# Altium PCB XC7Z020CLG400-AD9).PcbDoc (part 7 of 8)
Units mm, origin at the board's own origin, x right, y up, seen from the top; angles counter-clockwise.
Board outline 38 x 38 mm, 14 copper layers (Top Layer, GND02, ART03, PWR04, ART05, GND06, ART07, ART08, PWR09, ART10, GND11, ART12, PWR13, Bottom Layer); 276 components, 302 nets, 1684 pads, 1576 vias.
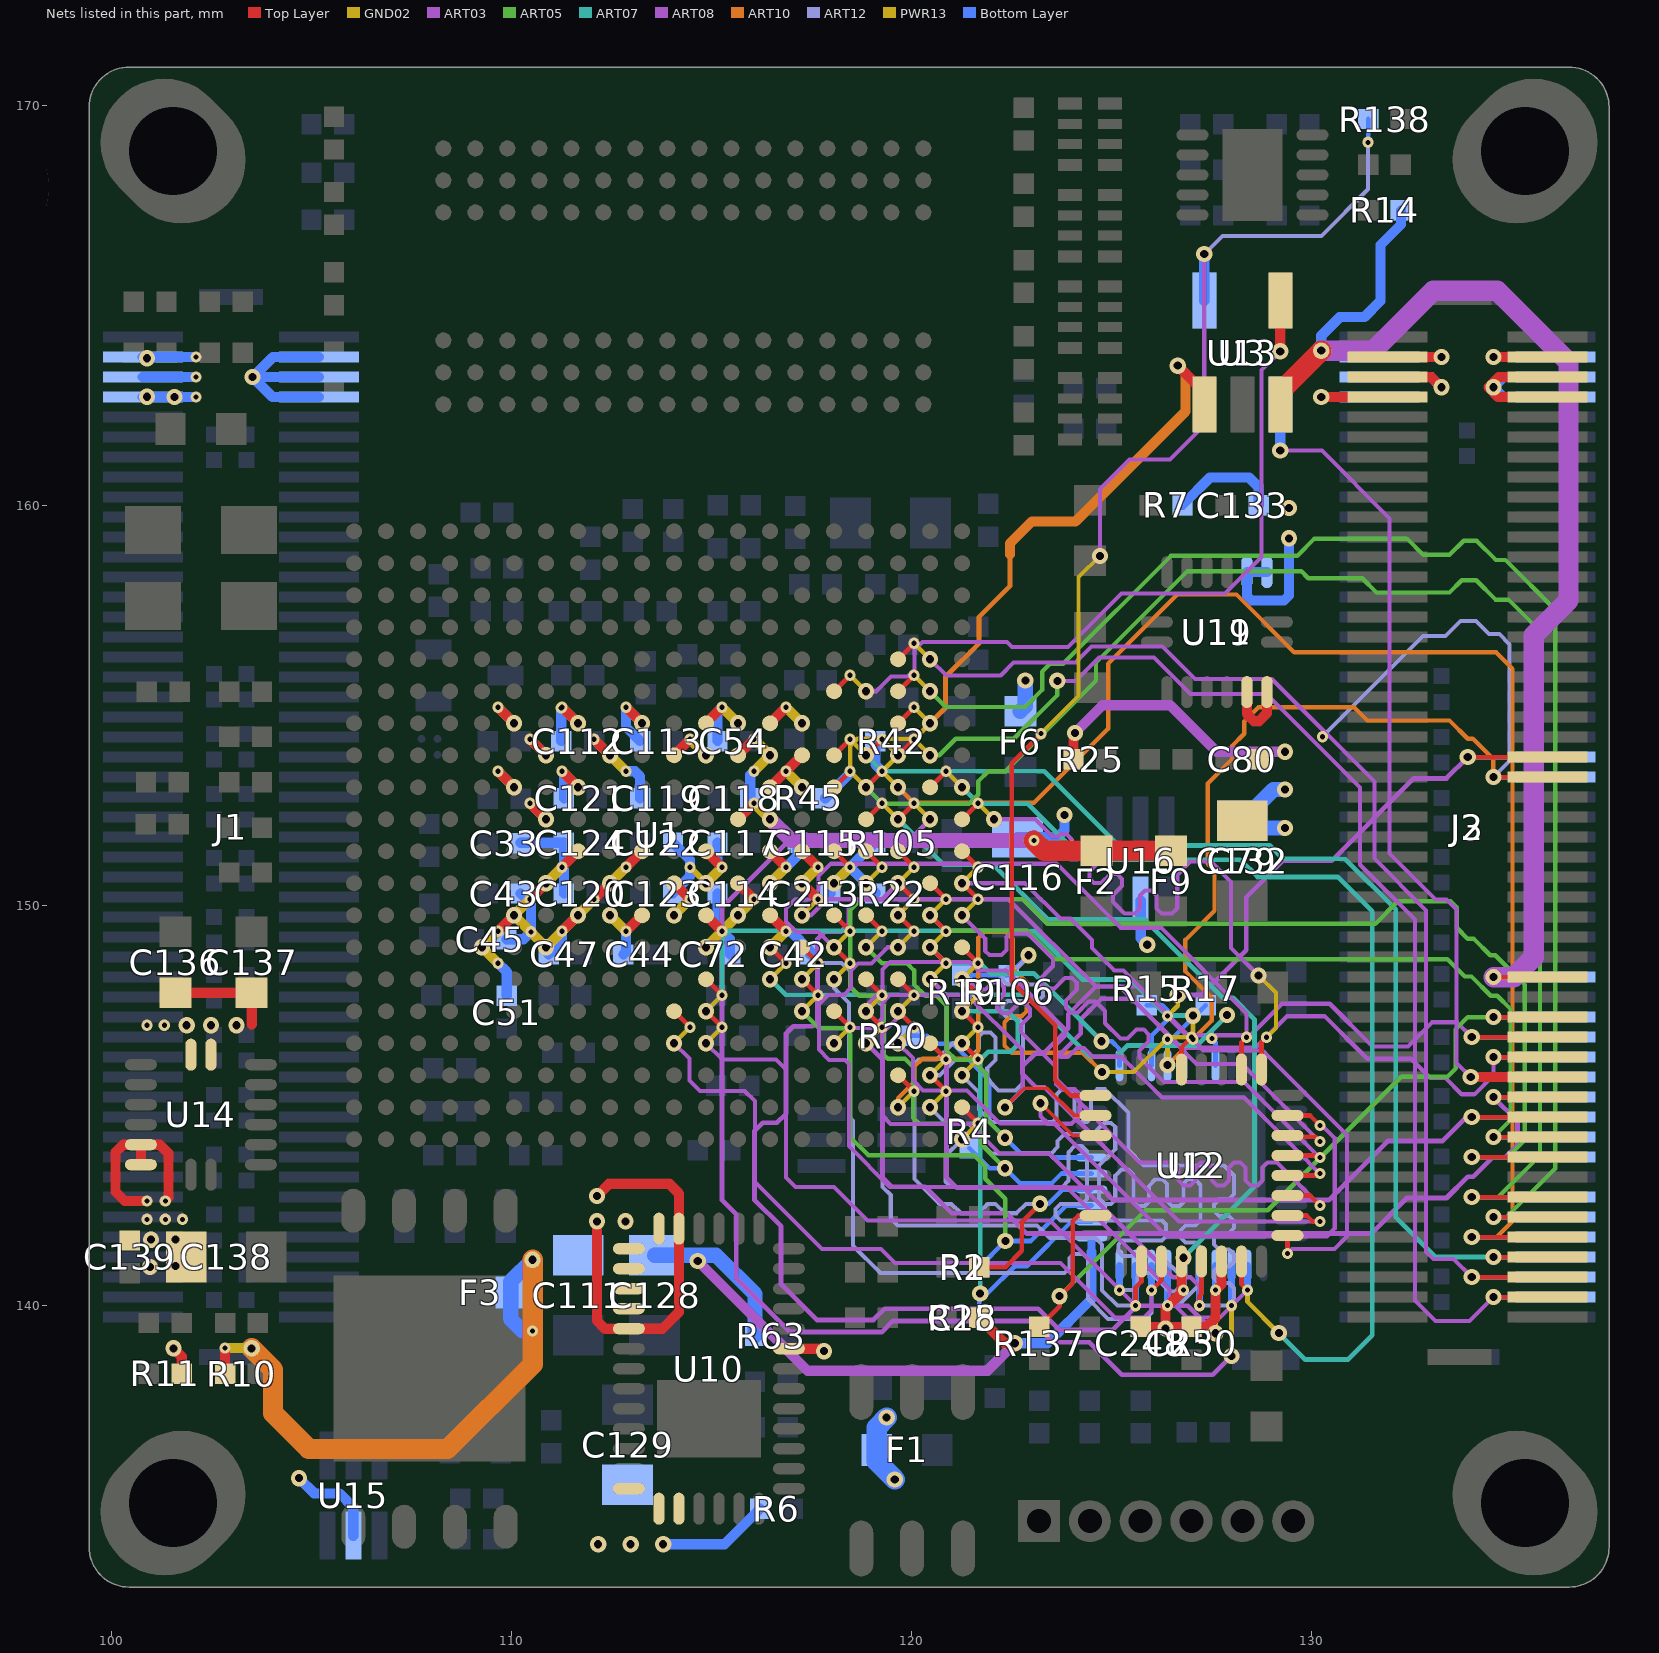
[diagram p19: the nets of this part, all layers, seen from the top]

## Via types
v1: diameter 0.406, hole 0.203, GND02 to PWR13, 466 vias
v2: diameter 0.279, hole 0.127, Top Layer to GND02, tented top, 373 vias
v3: diameter 0.406, hole 0.203, Top Layer to Bottom Layer, 324 vias
v4: diameter 0.279, hole 0.127, PWR13 to Bottom Layer, 207 vias
v5: diameter 0.279, hole 0.127, Top Layer to ART03, tented top, 41 vias
v6: diameter 0.279, hole 0.127, Top Layer to ART03, 40 vias
v7: diameter 0.279, hole 0.127, PWR13 to Bottom Layer, tented bottom, 39 vias
v8: diameter 0.279, hole 0.127, ART12 to Bottom Layer, 30 vias
v9: diameter 0.279, hole 0.127, Top Layer to GND02, 20 vias
v10: diameter 0.406, hole 0.203, Top Layer to Bottom Layer, tented both sides, 16 vias
v11: diameter 0.406, hole 0.203, ART03 to ART12, 11 vias
v12: diameter 0.406, hole 0.203, Top Layer to Bottom Layer, tented top, 9 vias

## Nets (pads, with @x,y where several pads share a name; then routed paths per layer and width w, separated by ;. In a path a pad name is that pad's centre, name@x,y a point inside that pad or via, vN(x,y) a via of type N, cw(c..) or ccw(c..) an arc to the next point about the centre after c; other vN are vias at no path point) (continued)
PHY_LED1: J2.29 J3.29 R15.1 U2.33 | length 17.4
  Top Layer w0.114: v3(133.905,153.719) J3.29@135.9,153.719
  ART08 w0.119: v1(126.657,147.772) 127.248,147.772 128.372,148.895 128.372,150.216 129.286,151.13 130.505,151.13 132.563,153.187 133.374,153.187 v3(133.905,153.719)
  PWR13 w0.114: v4(126.4,147.246) 126.657,147.503 v1(126.657,147.772)
  Bottom Layer w0.114: R15.1@125.882,147.52 126.267,147.52 126.4,147.387 v4(126.4,147.246) 126.4,147.152 126,146.752 U2.33@126,146.01 ; v3(133.905,153.719) J2.29@136.1,153.719
PHY_LED2: J2.28 J3.28 R17.1 U2.34 | length 32.5
  Top Layer w0.114: v3(134.548,153.219) J3.28@135.9,153.219
  ART10 w0.109: v1(126.4,146.025) 127.508,147.133 127.508,147.701 126.848,148.361 126.848,149.149 127.575,149.876 127.575,150.885 127.406,151.054 127.406,153.06 128.016,153.67 128.016,154 128.321,154.305 128.321,154.61 128.676,154.965 131.064,154.965 131.394,154.635 133.452,154.635 133.909,154.178 134.036,154.178 134.548,153.665 v3(134.548,153.219)
  ART12 w0.102: v8(130.277,154.229) 132.791,156.743 133.35,156.743 133.731,157.124 134.112,157.124 134.442,156.794 134.696,156.794 134.95,156.54 134.95,153.621 v3(134.548,153.219)
  PWR13 w0.114: v1(126.4,146.025) v4(126.4,146.666)
  Bottom Layer w0.114: U2.34@126.4,146.01 v4(126.4,146.666) 126.502,146.666 R17.1@127.356,147.52 ; v3(134.548,153.219) J2.28@136.1,153.219
PS-MIO-VREF: C213.1 R22.1 R105.2 U1.E11 | length 4.4
  Top Layer w0.114: U1.E11@118.065,151.365 v2(118.465,150.965)
  GND02 w0.109: v1(118.065,150.565) v2(118.465,150.965)
  PWR13 w0.254: v1(118.065,150.565) v2(118.465,150.965)
  Bottom Layer w0.254: C213.1@117.971,150.309 117.971,150.471 v2(118.465,150.965) ; R22.1@119.097,150.309 119.097,150.333 v2(118.465,150.965) ; R105.2@119.097,151.579 119.079,151.579 v2(118.465,150.965)
  other v4: 118.465,150.965
RGMII-CLK25M: U1.G14 U2.37 | length 15.2
  Top Layer w0.114: U1.G14@116.465,148.965 v2(116.865,148.565)
  ART12 w0.102: v8(127.508,146.685) 127.508,146.888 v1(127.889,147.269)
  GND02 w0.109: v1(116.465,148.165) v2(116.865,148.565)
  ART07 w0.119: v1(116.465,148.165) 116.853,147.777 122.911,147.777 124.46,146.228 125.12,146.228 125.4,146.507 127.127,146.507 v1(127.889,147.269)
  Bottom Layer w0.114: v8(127.508,146.685) 127.6,146.593 U2.37@127.6,146.01
RGMII-CLK125M: U1.J15 U2.35 | length 17.2
  Top Layer w0.114: U1.J15@114.865,148.165 v2(115.265,147.765)
  GND02 w0.109: v1(114.865,147.365) v2(115.265,147.765)
  ART07 w0.119: v1(114.865,147.365) v2(115.265,147.765) 115.265,149.2 115.443,149.377 123.063,149.377 124.282,148.158 125.476,148.158 126.378,147.256 v1(127.038,147.256)
  PWR13 w0.114: v4(127.038,146.666) v1(127.038,147.256)
  Bottom Layer w0.114: U2.35@126.8,146.01 126.8,146.428 v4(127.038,146.666)
RGMII-MDC: U1.C10 U2.13 | length 32.7
  Top Layer w0.114: U1.C10@119.665,152.165 v2(120.065,152.565)
  GND02 w0.109: v2(120.065,152.565) v1(120.465,152.165)
  ART08 w0.119: v1(120.465,152.165) 120.015,151.715 117.018,151.715 115.265,149.962 115.265,142.646 115.621,142.291 115.621,140.691 116.967,139.344 119.253,139.344 119.532,139.624 122.994,139.624 123.527,139.09 124.448,139.09 125.261,138.278 127.533,138.278 v1(128,138.744)
  PWR13 w0.114: v1(128,138.744) v4(128,140.005)
  Bottom Layer w0.178: v4(128,140.005) U2.13@128,141.01
RGMII-MDIO: R3.2 U1.C11 U2.14 | length 29.2
  Top Layer w0.114: U1.C11@119.665,151.365 v2(120.065,150.965)
  GND02 w0.109: v1(119.665,150.565) v2(120.065,150.965)
  ART08 w0.119: v1(119.665,150.565) 119.265,150.165 118.618,150.165 118.44,149.987 118.44,149.555 118.237,149.352 117.831,149.352 117.653,149.174 117.653,147.117 117.526,146.99 117.043,146.99 116.865,146.812 116.865,144.805 116.637,144.577 116.281,144.577 116.078,144.374 116.078,142.646 116.738,141.986 116.738,140.545 117.634,139.649 119.05,139.649 119.329,139.929 123.172,139.929 123.705,139.395 125.019,139.395 125.628,140.005 126.912,140.005 v1(127.6,139.317)
  PWR13 w0.114: v1(127.6,139.317) v4(127.6,140.392)
  Bottom Layer w0.114: R3.2@127,139.475 127.391,139.475 127.6,139.684 v4(127.6,140.392)
  Bottom Layer w0.178: v4(127.6,140.392) U2.14@127.6,141.01
RGMII-NINT: U1.B13 U2.31 | length 7.3
  Top Layer w0.114: U1.B13@120.465,149.765 v2(120.865,149.365)
  GND02 w0.109: v1(120.465,148.965) v2(120.865,149.365)
  ART07 w0.119: v1(120.465,148.965) 120.865,148.565 121.717,148.565 121.971,148.311 123.056,148.311 v3(124.752,146.615)
  Bottom Layer w0.114: v3(124.752,146.615) 125.006,146.615 125.2,146.421 U2.31@125.2,146.01
RGMII-NRST: U1.B9 U2.12 | length 28.1
  Top Layer w0.114: U1.B9@120.465,152.965 v2(120.865,153.365)
  GND02 w0.109: v2(120.865,153.365) v1(121.265,152.965)
  ART07 w0.119: v1(121.265,152.965) 121.678,152.552 122.911,152.552 124.308,151.155 128.219,151.155 128.651,150.724 130.658,150.724 131.521,149.86 131.521,139.268 130.912,138.659 129.845,138.659 v1(129.184,139.319)
  PWR13 w0.114: v4(128.4,140.392) 128.4,140.103 v1(129.184,139.319)
  Bottom Layer w0.178: v4(128.4,140.392) U2.12@128.4,141.01
RGMII-RXCLK: R19.1 R106.1 U1.B17 | length 13.2
  Top Layer w0.114: U1.B17@120.465,146.565 v2(120.865,146.165)
  ART12 w0.102: v1(120.465,145.765) 120.695,145.765 121.082,146.152 121.412,146.152 121.691,146.431 121.691,146.736 121.793,146.837 121.971,146.837 122.098,146.71 122.098,146.152 121.895,145.948 121.895,145.669 122.174,145.39 122.606,145.39 122.784,145.567 122.784,147.074 122.658,147.199 122.401,147.199 122.276,147.325 122.276,147.493 122.401,147.618 123.166,147.618 123.292,147.744 123.292,147.912 123.166,148.038 122.401,148.038 122.276,148.163 122.276,148.331 122.401,148.457 122.658,148.457 122.784,148.582 122.784,148.62 v3(122.928,148.764)
  GND02 w0.109: v1(120.465,145.765) v2(120.865,146.165)
  Bottom Layer w0.114: R19.1@121.265,148.264 R106.1@122.428,148.264 v3(122.928,148.764)
RGMII-RXCTL: R20.1 U1.D13 U2.26 | length 14.5
  Top Layer w0.114: U1.D13@118.865,149.765 v2(119.265,149.365)
  ART05 w0.109: v1(118.865,148.965) 119.265,148.565 119.888,148.565 120.066,148.387 120.066,148.031 120.345,147.752 120.625,147.752 120.879,147.498 120.879,146.38 121.107,146.152 121.514,146.152 121.869,145.796 121.869,144.672 v3(122.339,144.202)
  GND02 w0.109: v1(118.865,148.965) v2(119.265,149.365)
  Bottom Layer w0.114: R20.1@119.956,146.753 120.379,146.753 120.574,146.558 121.031,146.558 121.945,145.644 121.945,144.596 v3(122.339,144.202) 122.72,143.821 123.438,143.821 123.549,143.71 U2.26@124.5,143.71
RGMII-RXD0: R4.1 U1.D11 U2.25 | length 14.8
  Top Layer w0.114: U1.D11@118.865,151.365 v2(119.265,150.965)
  ART05 w0.109: v1(118.865,150.565) 118.865,150.285 118.466,149.885 118.466,147.98 118.694,147.752 119.075,147.752 119.304,147.523 119.304,146.279 119.405,146.177 119.837,146.177 120.04,145.974 120.04,144.704 120.193,144.551 121.514,144.551 121.742,144.323 121.742,144.037 v3(122.339,143.44)
  GND02 w0.109: v1(118.865,150.565) v2(119.265,150.965)
  Bottom Layer w0.114: R4.1@121.451,143.941 121.951,143.44 v3(122.339,143.44) 122.72,143.059 123.501,143.059 123.752,143.31 U2.25@124.5,143.31
RGMII-RXD1: R1.1 U1.A16 U2.24 | length 13.2
  Top Layer w0.114: U1.A16@121.265,147.365 v2(121.665,146.965) ; R1.1@121.695,140.97 122.352,140.97 122.758,141.376 122.758,142.094 v3(123.215,142.551)
  ART12 w0.102: v1(121.265,146.565) 121.038,146.565 120.632,146.159 120.174,146.159 120.073,146.057 120.073,143.173 120.695,142.551 121.006,142.551 121.24,142.316 121.66,142.316 121.895,142.551 122.098,142.551 122.333,142.316 122.625,142.316 122.86,142.551 v3(123.215,142.551)
  GND02 w0.109: v1(121.265,146.565) v2(121.665,146.965)
  Bottom Layer w0.114: v3(123.215,142.551) 123.425,142.551 123.784,142.91 U2.24@124.5,142.91
RGMII-RXD2: R2.1 U1.F15 U2.23 | length 14.4
  Top Layer w0.114: U1.F15@117.265,148.165 v2(117.665,147.765)
  ART05 w0.109: v1(117.265,147.365) 117.691,146.939 118.313,146.939 118.466,146.787 118.466,144.221 118.923,143.764 121.564,143.764 121.844,143.485 121.844,143.18 122.347,142.677 v3(122.347,141.622)
  GND02 w0.109: v1(117.265,147.365) v2(117.665,147.765)
  Bottom Layer w0.114: R2.1@121.695,140.97 v3(122.347,141.622) 122.978,141.622 123.866,142.51 U2.23@124.5,142.51
  Bottom Layer w0.381: R2.1@121.695,140.97 R2.1@121.695,141.018
RGMII-RXD3: R18.2 U1.A15 U2.22 | length 14.3
  Top Layer w0.114: U1.A15@121.265,148.165 v2(121.665,147.765)
  GND02 w0.109: v1(121.265,147.365) v2(121.665,147.765)
  ART07 w0.119: v1(121.265,147.365) 122.408,147.365 122.657,147.117 122.657,146.533 122.479,146.355 121.92,146.355 121.717,146.152 v3(121.717,140.31)
  Bottom Layer w0.114: R18.2@121.695,139.7 v3@121.695,140.288 ; v3@121.717,140.288 v3@121.695,140.288 ; U2.22@124.5,142.11 124,142.11 122.885,140.995 122.58,140.995 121.895,140.31 v3(121.717,140.31) v3@121.695,140.288
RGMII-TXCLK: U1.A19 U2.20 | length 18.5
  Top Layer w0.114: U1.A19@121.265,144.965 v2(121.665,144.565)
  ART12 w0.102: v1(121.265,144.165) 120.853,143.753 120.853,143.104 120.98,142.977 123.774,142.977 123.927,143.129 123.927,143.84 124.079,143.993 124.257,143.993 124.384,143.866 124.384,142.672 124.257,142.545 123.723,142.545 123.596,142.418 123.596,142.265 123.723,142.138 126.263,142.138 126.365,142.037 126.365,141.732 126.263,141.63 125.273,141.63 125.171,141.529 125.171,141.351 125.273,141.249 126.238,141.249 126.771,140.716 126.771,140.538 126.594,140.36 126.445,140.36 125.987,140.818 125.755,140.818 125.654,140.716 125.654,140.487 125.558,140.392 v8(125.2,140.392)
  GND02 w0.109: v1(121.265,144.165) v2(121.665,144.565)
  Bottom Layer w0.178: v8(125.2,140.392) U2.20@125.2,141.01
RGMII-TXCTL: U1.F14 U2.19 | length 18.1
  Top Layer w0.114: U1.F14@117.265,148.965 v2(117.665,148.565)
  ART12 w0.102: v1(117.265,148.165) 117.672,148.572 118.255,148.572 118.472,148.355 118.472,147.98 118.676,147.777 118.999,147.777 119.278,147.498 119.278,142.977 119.482,142.773 119.482,142.189 119.659,142.011 123.139,142.011 123.457,141.694 124.6,141.694 124.765,141.529 124.765,140.386 125.146,140.005 v8(125.6,140.005)
  GND02 w0.109: v1(117.265,148.165) v2(117.665,148.565)
  Bottom Layer w0.178: v8(125.6,140.005) U2.19@125.6,141.01
RGMII-TXD0: U1.E14 U2.18 | length 18.6
  Top Layer w0.114: U1.E14@118.065,148.965 v2(118.465,148.565)
  ART12 w0.102: v1(118.065,148.165) 118.065,147.949 118.44,147.574 118.44,144.729 118.542,144.628 118.542,141.503 119.228,140.818 123.825,140.818 123.952,140.945 123.952,141.199 124.054,141.3 124.282,141.3 124.409,141.173 124.409,140.183 124.917,139.675 125.857,139.675 126,139.818 v8(126,140.392)
  GND02 w0.109: v1(118.065,148.165) v2(118.465,148.565)
  Bottom Layer w0.178: v8(126,140.392) U2.18@126,141.01
RGMII-TXD1: U1.B18 U2.17 | length 19.7
  Top Layer w0.114: U1.B18@120.465,145.765 v2(120.865,145.365)
  ART12 w0.102: v1(120.465,144.965) 120.879,144.551 121.437,144.551 121.717,144.272 121.717,144.094 121.996,143.815 123.495,143.815 123.647,143.967 123.647,144.12 123.825,144.297 124.536,144.297 124.816,144.577 124.993,144.577 125.095,144.475 125.095,143.916 124.689,143.51 124.689,142.697 124.841,142.545 124.993,142.545 125.095,142.646 125.095,143.256 125.247,143.408 125.425,143.408 125.552,143.281 125.552,142.596 125.654,142.494 125.832,142.494 125.933,142.596 125.933,143.002 126.086,143.154 126.289,143.154 126.39,143.053 126.39,142.621 126.517,142.494 126.695,142.494 126.797,142.596 126.797,143.053 126.898,143.154 127.102,143.154 127.229,143.027 127.229,142.131 127.103,142.005 126.846,142.005 126.721,141.879 126.721,141.712 126.846,141.586 127.103,141.586 127.229,141.46 127.229,140.564 126.67,140.005 v8(126.4,140.005)
  GND02 w0.109: v1(120.465,144.965) v2(120.865,145.365)
  Bottom Layer w0.178: v8(126.4,140.005) U2.17@126.4,141.01
RGMII-TXD2: U1.D10 U2.16 | length 20.2
  Top Layer w0.114: U1.D10@118.865,152.165 v2(119.265,152.565)
  GND02 w0.109: v2(119.265,152.565) v1(119.665,152.165)
  ART07 w0.119: v1(119.665,152.165) 120.802,151.028 122.047,151.028 123.419,149.657 125.832,149.657 127.787,147.701 128.041,147.701 128.575,147.168 128.575,142.977 v1(126.8,141.202)
  PWR13 w0.109: v4(126.8,140.392) v1(126.8,141.202)
  Bottom Layer w0.178: v4(126.8,140.392) U2.16@126.8,141.01
RGMII-TXD3: U1.A17 U2.15 | length 19.3
  Top Layer w0.114: U1.A17@121.265,146.565 v2(121.665,146.165)
  ART12 w0.102: v1(121.265,145.765) 121.691,145.339 121.691,144.907 121.996,144.602 123.52,144.602 123.622,144.704 123.622,145.288 123.749,145.415 123.927,145.415 124.079,145.263 124.079,144.704 124.181,144.602 124.384,144.602 124.485,144.704 124.485,145.263 124.638,145.415 124.841,145.415 125.425,144.831 125.425,143.891 125.806,143.51 127.813,143.51 128.067,143.256 128.067,142.791 127.941,142.665 127.685,142.665 127.559,142.54 127.559,142.372 127.685,142.246 127.941,142.246 128.067,142.121 128.067,141.953 127.941,141.827 127.685,141.827 127.559,141.702 127.559,141.534 127.685,141.408 127.941,141.408 128.067,141.282 128.067,141.115 127.941,140.989 127.685,140.989 127.559,140.863 127.559,140.696 127.685,140.57 127.941,140.57 128.067,140.444 128.067,140.157 127.915,140.005 v8(127.2,140.005)
  GND02 w0.109: v1(121.265,145.765) v2(121.665,146.165)
  Bottom Layer w0.178: v8(127.2,140.005) U2.15@127.2,141.01
SPI1_CLK_CAN1_RX: J2.10 J3.10 U1.B12 | length 22.9
  Top Layer w0.114: U1.B12@120.465,150.565 v2(120.865,150.165) ; v3(134.548,144.219) J3.10@135.9,144.219
  ART05 w0.109: v1(120.465,149.765) 120.853,149.377 122.885,149.377 123.594,148.669 133.398,148.669 133.833,148.234 134,148.234 134.483,147.752 134.645,147.752 134.976,147.422 134.976,144.646 v3(134.548,144.219)
  GND02 w0.109: v1(120.465,149.765) v2(120.865,150.165)
  Bottom Layer w0.114: v3(134.548,144.219) J2.10@136.1,144.219
SPI1_CS0_CAN1_TX: J2.9 J3.9 U1.C12 | length 28
  Top Layer w0.114: U1.C12@119.665,150.565 v2(120.065,150.165) ; v3(134.007,143.719) J3.9@135.9,143.719
  ART05 w0.109: v1(119.665,149.765) 120.04,150.14 120.04,150.165 ; v2(120.065,150.165) 122.784,150.165 123.393,149.555 131.597,149.555 132.156,150.114 133.477,150.114 133.629,149.962 133.629,149.454 133.909,149.174 134.061,149.174 134.468,148.768 134.595,148.768 135.331,148.031 135.331,144.145 134.905,143.719 v3(134.007,143.719)
  GND02 w0.109: v1(119.665,149.765) v2(120.065,150.165)
  Bottom Layer w0.114: v3(134.007,143.719) J2.9@136.1,143.719
SPI1_MISO_CAN0_TX: J2.11 J3.11 U1.B14 | length 24.5
  Top Layer w0.114: U1.B14@120.465,148.965 v2(120.865,148.565) ; v3(134.007,144.719) J3.11@135.9,144.719
  GND02 w0.109: v1(120.465,148.165) v2(120.865,148.565)
  ART08 w0.119: v1(120.465,148.165) 120.879,147.751 120.879,143.205 121.133,142.951 124.739,142.951 125.044,142.646 130.429,142.646 131.902,144.12 133.274,144.12 133.873,144.719 v3(134.007,144.719)
  Bottom Layer w0.114: v3(134.007,144.719) J2.11@136.1,144.719
SPI1_MOSI_CAN0_RX: J2.12 J3.12 U1.D16 | length 26.4
  Top Layer w0.114: U1.D16@118.865,147.365 v2(119.265,146.965) ; v3(134.548,145.219) J3.12@135.9,145.219
  GND02 w0.109: v1(118.865,146.565) v2(119.265,146.965)
  ART08 w0.119: v1(118.865,146.565) 119.278,146.152 119.278,143.205 119.507,142.977 120.345,142.977 121.006,142.316 122.377,142.316 122.885,141.808 131.496,141.808 132.385,142.697 133.375,142.697 133.909,143.231 134.044,143.231 134.527,143.713 134.849,143.713 135.153,144.018 135.153,144.614 v3(134.548,145.219)
  Bottom Layer w0.114: v3(134.548,145.219) J2.12@136.1,145.219
UART-RXA: J2.7 J3.7 U1.E9 | length 41.1
  Top Layer w0.114: U1.E9@118.065,152.965 v2(118.465,153.365) ; v3(134.007,142.719) J3.7@135.9,142.719
  ART05 w0.109: v1(118.865,152.965) 119.278,152.552 121.437,152.552 121.666,152.781 121.666,153.111 121.92,153.365 122.352,153.365 124.612,155.626 124.612,156.083 126.898,158.369 129.743,158.369 129.921,158.191 131.267,158.191 131.623,157.836 133.452,157.836 133.756,158.14 134.119,158.14 134.601,157.658 134.925,157.658 135.712,156.87 135.712,143.761 134.671,142.719 v3(134.007,142.719)
  GND02 w0.109: v2(118.465,153.365) v1(118.865,152.965)
  Bottom Layer w0.114: v3(134.007,142.719) J2.7@136.1,142.719
UART-RXB: J2.4 J3.4 U1.E8 | length 29.4
  Top Layer w0.114: U1.E8@118.065,153.765 v2(118.465,154.165) ; v3(134.548,141.219) J3.4@135.9,141.219
  GND02 w0.109: v2(118.465,154.165) v1(118.865,153.765)
  ART07 w0.119: v1(118.865,153.765) 119.265,153.365 123.317,153.365 125.171,151.511 128.956,151.511 129.286,151.181 130.835,151.181 132.105,149.911 132.105,142.215 133.101,141.219 v3(134.548,141.219)
  Bottom Layer w0.114: v3(134.548,141.219) J2.4@136.1,141.219
UART-TXA: J2.6 J3.6 U1.C6 | length 38.9
  Top Layer w0.114: U1.C6@119.665,155.365 v2(120.065,155.765) ; v3(134.548,142.219) J3.6@135.9,142.219
  ART05 w0.109: v1(120.465,155.365) 120.858,154.972 122.841,154.972 123.266,155.397 123.266,155.854 123.469,156.058 123.793,156.058 126.485,158.75 129.642,158.75 130.073,159.182 132.385,159.182 132.791,158.775 133.452,158.775 133.807,159.131 134.128,159.131 134.611,158.648 134.849,158.648 136.093,157.404 136.093,143.434 134.879,142.219 v3(134.548,142.219)
  GND02 w0.109: v2(120.065,155.765) v1(120.465,155.365)
  Bottom Layer w0.114: v3(134.548,142.219) J2.6@136.1,142.219
UART-TXB: J2.5 J3.5 U1.D9 | length 39.5
  Top Layer w0.114: U1.D9@118.865,152.965 v2(119.265,153.365) ; v3(134.007,141.719) J3.5@135.9,141.719
  ART10 w0.109: v1(119.665,152.965) 120.052,152.578 123.063,152.578 124.917,154.432 124.917,156.058 126.644,157.785 128.124,157.785 129.572,156.337 134.62,156.337 135.026,155.931 135.026,142.113 134.633,141.719 v3(134.007,141.719)
  GND02 w0.109: v2(119.265,153.365) v1(119.665,152.965)
  Bottom Layer w0.114: v3(134.007,141.719) J2.5@136.1,141.719
USB0-CLK: U1.J16 U12.26 | length 17.3
  Top Layer w0.114: U1.J16@114.865,147.365 v2(115.265,146.965) ; v6(125.6,140.005) 125.6,140.459 125.75,140.609 U12.26@125.75,141.11
  ART03 w0.102: v1(114.865,146.565) 115.271,146.159 116.618,146.159 116.865,145.911 116.865,143.212 117.101,142.977 118.059,142.977 118.897,142.138 123.467,142.138 v6(125.6,140.005)
  GND02 w0.109: v1(114.865,146.565) v2(115.265,146.965)
USB0-CLKO: U1.A11 U12.1 | length 18.1
  Top Layer w0.114: U1.A11@121.265,151.365 v2(121.665,150.965) ; v6(129.4,141.313) U12.1@129.4,141.76
  ART03 w0.102: v1(121.265,150.565) 122.841,150.565 123.723,149.682 123.977,149.682 124.511,149.149 124.511,148.946 125.07,148.387 125.298,148.387 127.305,146.38 128.778,146.38 130.886,144.272 130.886,141.732 130.576,141.422 129.508,141.422 v6(129.4,141.313)
  GND02 w0.109: v1(121.265,150.565) v2(121.665,150.965)
USB0-CPEN: R138.1 U12.17 U13.4 | length 32.5
  Top Layer w0.114: v9(123.241,154.305) 122.504,153.568 122.504,148.107 123.596,147.015 123.596,145.644 123.98,145.26 U12.17@124.6,145.26
  ART03 w0.102: v1(124.714,158.75) 124.714,160.426 125.451,161.163 126.467,161.163 127.32,162.016 v3(127.32,166.295)
  ART12 w0.102: v3(127.32,166.295) 127.776,166.751 130.251,166.751 131.416,167.916 v8(131.416,169.089)
  GND02 w0.102: v9(123.241,154.305) 124.181,155.245 124.181,158.217 v1(124.714,158.75)
  Bottom Layer w0.114: v8@131.416,169.084 v8(131.416,169.089) R138.1@131.416,169.672
  Bottom Layer w0.254: U13.4@127.32,165.13 v3(127.32,166.295)
USB0-D0: U1.A14 U12.3 | length 17.6
  Top Layer w0.114: U1.A14@121.265,148.965 v2(121.665,148.565) ; U12.3@129.4,142.76 129.963,142.76 v6(130.213,142.51)
  ART03 w0.102: v1(121.265,148.165) 121.419,148.165 121.67,147.914 121.848,147.914 122.018,148.083 122.195,148.083 122.314,147.965 122.314,147.787 122.144,147.617 122.144,147.439 122.263,147.321 122.441,147.321 122.667,147.547 122.845,147.547 122.963,147.429 122.963,147.251 122.737,147.025 122.737,146.847 123.596,145.987 123.596,145.694 125.705,143.586 126.55,143.586 126.676,143.46 126.676,143.14 126.802,143.015 126.97,143.015 127.095,143.14 127.095,143.46 127.221,143.586 127.389,143.586 127.514,143.46 127.514,143.14 127.64,143.015 127.808,143.015 127.933,143.14 127.933,143.46 128.059,143.586 128.227,143.586 128.353,143.46 128.353,143.14 128.478,143.015 128.646,143.015 128.772,143.14 128.772,143.46 128.897,143.586 129.137,143.586 v6(130.213,142.51)
  GND02 w0.109: v1(121.265,148.165) v2(121.665,148.565)
USB0-D1: U1.D15 U12.4 | length 17.1
  Top Layer w0.114: U1.D15@118.865,148.165 v2(119.265,147.765) ; U12.4@129.4,143.26 130.163,143.26 v6(130.213,143.31)
  ART03 w0.102: v1@118.865,147.491 119.273,147.899 119.273,148.407 119.463,148.597 121.456,148.597 121.666,148.387 122.377,148.387 123.837,146.927 123.837,146.749 123.611,146.522 123.611,146.345 123.73,146.226 123.908,146.226 124.134,146.452 124.312,146.452 124.536,146.228 125.247,146.228 126.263,145.212 128.311,145.212 129.921,143.602 ; 129.921,143.589 v6@130.2,143.31
  GND02 w0.109: v1(118.865,147.365) v2(119.265,147.765)
USB0-D2: U1.A12 U12.5 | length 17.2
  Top Layer w0.114: U1.A12@121.265,150.565 v2(121.665,150.165) ; U12.5@129.4,143.76 130.163,143.76 v6(130.213,143.71)
  ART03 w0.102: v1(121.265,149.765) 121.844,149.186 121.844,148.869 121.945,148.768 122.25,148.768 122.377,148.895 122.377,149.206 122.479,149.307 122.905,149.307 123.539,148.673 123.539,148.495 123.268,148.224 123.268,148.046 123.386,147.928 123.564,147.928 123.835,148.199 124.013,148.199 124.131,148.08 124.131,147.902 123.86,147.631 123.86,147.453 123.979,147.335 124.157,147.335 124.428,147.606 124.606,147.606 124.841,147.371 124.841,147.066 125.225,146.682 125.403,146.682 125.63,146.908 125.807,146.908 125.926,146.789 125.926,146.611 125.7,146.385 125.7,146.207 126.314,145.593 128.317,145.593 v6@130.2,143.71
  GND02 w0.109: v1(121.265,149.765) v2(121.665,150.165)
USB0-D3: U1.F12 U12.6 | length 17.6
  Top Layer w0.114: U12.6@129.4,144.26 129.436,144.224 130.099,144.224 v6(130.213,144.11)
  Top Layer w0.254: U1.F12@117.265,150.565 v2(117.665,150.165)
  ART03 w0.102: v1(117.265,149.765) 117.482,149.765 117.882,150.165 122.428,150.165 124.612,147.98 125.197,147.98 127.127,146.05 128.26,146.05 130.2,144.11 v6(130.213,144.11)
  GND02 w0.109: v1(117.265,149.765) v2(117.665,150.165)
USB0-D4: U1.C16 U12.7 | length 18.1
  Top Layer w0.114: U1.C16@119.665,147.365 v2(120.065,146.965) ; U12.7@129.4,144.76 129.963,144.76 v6(130.213,144.51)
  ART03 w0.102: v1(119.665,146.565) 120.035,146.196 120.035,145.644 120.289,145.39 121.387,145.39 122.219,144.558 123.565,144.558 126.383,141.739 130.385,141.739 130.581,141.935 130.581,144.196 130.267,144.51 v6(130.213,144.51)
  GND02 w0.109: v1(119.665,146.565) v2(120.065,146.965)
USB0-D5: U1.A10 U12.9 | length 17.6
  Top Layer w0.114: U1.A10@121.265,152.165 v2(121.665,152.565) ; U12.9@128.75,145.91 128.75,146.589 v9(128.877,146.716)
  ART03 w0.102: v1(122.065,152.165) 123.095,152.165 123.52,151.74 123.673,151.74 123.731,151.797 123.875,151.797 124.018,151.653 124.018,151.51 123.876,151.367 123.876,151.257 123.973,151.16 124.151,151.16 124.377,151.386 124.555,151.386 124.674,151.267 124.674,151.09 124.447,150.863 124.447,150.685 124.566,150.567 124.744,150.567 124.97,150.793 125.148,150.793 125.266,150.675 125.266,150.497 125.04,150.271 125.04,150.093 125.324,149.809 125.585,149.809 125.711,149.935 125.711,150.255 125.837,150.381 126.004,150.381 126.13,150.255 126.13,149.935 126.256,149.809 126.517,149.809 126.644,149.936 126.644,150.774 126.975,151.105 127.483,151.105 127.991,150.597 127.991,148.946 v1(128.676,148.26)
  GND02 w0.102: v1(128.676,148.26) 129.108,147.828 129.108,146.947 v9(128.877,146.716)
  GND02 w0.109: v2(121.665,152.565) v1(122.065,152.165)
USB0-D6: U1.E13 U12.10 | length 18.1
  Top Layer w0.114: U1.E13@118.065,149.765 v2(118.465,149.365) ; U12.10@128.25,145.91 128.25,146.589 v6(128.377,146.716)
  ART03 w0.102: v1(118.065,148.965) 117.678,149.352 117.119,149.352 116.865,149.606 116.865,149.936 117.094,150.165 117.45,150.165 117.678,150.393 117.678,150.749 117.983,151.054 123.622,151.054 125.222,149.454 126.238,149.454 128.377,147.315 v6(128.377,146.716)
  GND02 w0.109: v1(118.065,148.965) v2(118.465,149.365)
USB0-D7: U1.C18 U12.13 | length 17.3
  Top Layer w0.114: U1.C18@119.665,145.765 v2(120.065,145.365) ; U12.13@126.75,145.91 126.75,146.462 v9(127.004,146.716)
  ART10 w0.109: v1(119.665,144.965) 119.665,145.192 120.066,145.593 120.066,145.974 120.269,146.177 121.463,146.177 121.666,146.38 121.666,149.2 121.818,149.352 122.352,149.352 122.53,149.174 122.53,148.438 122.885,148.082 122.885,147.371 122.758,147.244 122.479,147.244 122.326,147.091 122.326,146.507 122.504,146.329 124.282,146.329 v1(124.765,145.847)
  GND02 w0.102: v1(124.765,145.847) 125.552,145.847 126.421,146.716 v9(127.004,146.716)
  GND02 w0.109: v1(119.665,144.965) v2(120.065,145.365)
USB0-DIR: U1.C13 U12.31 | length 21
  Top Layer w0.114: U1.C13@119.665,149.765 v2(120.065,149.365) ; U12.31@128.25,141.11 128.25,140.542 v6(128.4,140.392)
  ART03 w0.102: v1(119.665,148.965) 119.399,148.965 118.999,148.565 118.669,148.565 118.491,148.387 118.491,147.955 118.313,147.777 117.914,147.777 117.685,147.549 117.685,146.406 117.939,146.152 118.339,146.152 118.44,146.05 118.44,143.993 119.456,142.977 123.876,142.977 126.448,140.404 126.448,140.152 126.893,139.707 127.715,139.707 v6(128.4,140.392)
  GND02 w0.109: v1(119.665,148.965) v2(120.065,149.365)
USB0-DM: J2.14 J3.14 U12.19 | length 22
  Top Layer w0.089: v3(123.228,145.066) 124.034,144.26 U12.19@124.6,144.26
  Top Layer w0.114: v3(134.548,146.219) J3.14@135.9,146.219
  ART08 w0.107: v3(123.228,145.066) 123.228,144.742 123.419,144.551 124.003,144.551 124.206,144.755 124.206,145.288 124.079,145.415 123.749,145.415 123.622,145.542 123.622,146.202 124.231,146.812 124.231,147.168 124.739,147.676 125.527,147.676 126.746,146.456 128.607,146.456 129.394,147.244 130.327,147.244 131.394,146.177 132.486,146.177 132.969,145.694 133.35,145.694 133.756,145.288 134.071,145.288 134.548,145.765 v3(134.548,146.219)
  Bottom Layer w0.114: v3(134.548,146.219) J2.14@136.1,146.219
USB0-DP: J2.15 J3.15 U12.18 | length 21.9
  Top Layer w0.089: v3(122.339,144.964) 122.815,145.44 123.393,145.44 124.074,144.76 U12.18@124.6,144.76
  Top Layer w0.114: v3(134.007,146.719) J3.15@135.9,146.719
  ART08 w0.107: v3(122.339,144.964) 122.784,145.409 122.784,145.994 123.093,146.304 123.285,146.304 123.922,146.94 123.922,147.296 124.611,147.985 125.655,147.985 126.874,146.766 128.478,146.766 129.266,147.554 130.456,147.554 131.523,146.487 132.415,146.487 133.016,147.087 133.639,147.087 v3(134.007,146.719)
  Bottom Layer w0.114: v3(134.007,146.719) J2.15@136.1,146.719
USB0-ID: J2.16 J3.16 R137.1 U12.23 | length 20.8
  Top Layer w0.114: R137.1@123.19,139.475 123.702,139.987 v3(123.702,140.243) 124.028,140.569 124.028,142.113 124.175,142.26 U12.23@124.6,142.26 ; v3(134.548,147.219) J3.16@135.9,147.219
  ART05 w0.109: v3(123.702,140.243) 125.852,142.392 128.905,142.392 132.243,145.73 133.398,145.73 133.61,145.942 133.61,146.92 133.91,147.219 v3(134.548,147.219)
  Bottom Layer w0.114: v3(134.548,147.219) J2.16@136.1,147.219
USB0-NXT: U1.E16 U12.2 | length 17.6
  Top Layer w0.114: U1.E16@118.065,147.365 v2(118.465,146.965) ; U12.2@129.4,142.26 129.876,142.26 130.026,142.11 v6(130.213,142.11)
  ART03 w0.102: v1(118.065,146.565) 118.446,146.946 119.019,146.946 119.273,147.2 119.273,147.581 119.463,147.772 121.392,147.772 122.758,146.406 122.758,145.82 123.112,145.466 123.331,145.466 126.686,142.11 v6(130.213,142.11)
  GND02 w0.109: v1(118.065,146.565) v2(118.465,146.965)
USB0-RST: U1.K16 U12.27 | length 18.8
  Top Layer w0.114: U1.K16@114.065,147.365 v2(114.465,146.965) ; v6(126,140.392) 126.25,140.642 U12.27@126.25,141.11
  ART03 w0.102: v1(114.065,146.565) 114.447,146.183 114.447,145.638 114.713,145.371 115.831,145.371 116.085,145.117 116.085,143.097 117.76,141.422 119.233,141.422 119.583,141.072 123.723,141.072 125.088,139.707 125.813,139.707 126,139.894 v6(126,140.392)
  GND02 w0.109: v1(114.065,146.565) v2(114.465,146.965)
USB0-STP: U1.C15 U12.29 | length 15.2
  Top Layer w0.114: U1.C15@119.665,148.165 v2(120.065,147.765) ; v6(127.2,140.005) 127.2,140.254 127.25,140.304 U12.29@127.25,141.11
  ART03 w0.102: v1(119.665,147.365) 119.665,147.212 119.273,146.819 119.273,144.755 119.476,144.551 121.463,144.551 122.199,143.815 123.444,143.815 126.543,140.716 126.975,140.716 127.2,140.491 v6(127.2,140.005)
  GND02 w0.109: v1(119.665,147.365) v2(120.065,147.765)
USB0-VBUS: J2.13 J3.13 U13.1 | length 23.5
  Top Layer w0.254: v3@134.007,145.719 J3.13@135.9,145.719
  ART03 w0.102: v3(129.22,161.385) 130.258,161.385 131.953,159.69 131.953,151.308 133.096,150.165 133.375,150.165 133.629,149.911 133.629,146.071 v3(133.982,145.719)
  Bottom Layer w0.254: v3(129.22,161.385) U13.1@129.22,162.53 ; v3@134.007,145.719 J2.13@136.1,145.719
VCC-1V0: C25.2 C42.1 C43.1 C44.1 C45.1 C47.1 C51.1 C54.1 C72.1 C111.1 C112.1 C113.1 C114.1 C115.1 C128.1 F2.1 F9.1 R63.1 U1.G7 U1.G11 U1.G13 U1.H10 U1.H12 U1.J7 U1.J13 U1.K12 U1.L7 U1.L13 U1.M12 U1.N7 U1.N13 U1.P8 U1.P12 U1.R7 U1.R13 U2.21 U10.5 U10.6 U10.7 U10.8 U10.9 U10.10 U10.11 | length 75.3
  Top Layer w0.254: v2(109.665,149.365) v1(110.065,149.765) ; v2(109.665,154.965) v1(110.065,154.565) ; v2(110.465,150.165) U1.P12@110.865,150.565 ; v2(110.465,154.165) v1(110.865,153.765) ; v4(111.265,149.365) v1(111.665,149.765) ; v2(111.265,154.965) v1(111.665,154.565) ; v2(112.065,150.165) U1.M12@112.465,150.565 ; v3(112.141,142.113) 112.141,139.624 112.335,139.43 U10.11@112.935,139.43 113.776,139.43 114.185,139.839 U10.5@114.185,141.93 114.185,142.812 113.944,143.053 112.446,143.053 v3(112.141,142.748) ; v4(112.865,149.365) U1.L13@113.265,149.765 ; v2(112.865,154.965) v1(113.265,154.565) ; U1.K12@114.065,150.565 v2(114.465,150.165) ; U1.J13@114.865,149.765 v2(115.265,149.365) ; U1.J7@114.865,154.565 v4(115.265,154.965) ; U1.H12@115.665,150.565 v2(116.065,150.165) ; U1.H10@115.665,152.165 v2(116.065,152.565) ; U1.G13@116.465,149.765 v2(116.865,149.365) ; U1.G11@116.465,151.365 v2(116.865,150.965) ; U1.G7@116.465,154.565 v2(116.865,154.965) ; C25.2@121.695,139.7 122.33,139.065 v3(122.58,139.065)
  Top Layer w0.508: v6(123.059,151.634) 123.313,151.38 F2.1@124.625,151.38 F9.1@126.49,151.38
  ART03 w0.254: v3(114.656,141.122) 117.399,138.379 121.895,138.379 v3(122.58,139.065)
  ART03 w0.381: v1(116.465,152.165) 116.996,151.634 v6(123.059,151.634)
  GND02 w0.254: v1(109.265,148.965) v2(109.665,149.365) ; v2(109.665,154.965) v1(110.065,154.565) ; v1(110.065,149.765) v2(110.465,150.165) ; v2(110.465,154.165) v1(110.865,153.765) ; v1(110.865,148.965) v4(111.265,149.365) ; v2(111.265,154.965) v1(111.665,154.565) ; v1(111.665,149.765) v2(112.065,150.165) ; v1(112.465,149.765) v4(112.865,149.365) ; v2(112.865,154.965) v1(113.265,154.565) ; v1(114.065,149.765) v2(114.465,150.165) ; v1(114.865,148.965) v2(115.265,149.365) ; v4(115.265,154.965) v1(115.665,154.565) ; v1(115.665,149.765) v2(116.065,150.165) ; v2(116.065,152.565) v1(116.465,152.165) ; v1(116.465,148.965) v2(116.865,149.365) ; v1(116.465,150.565) v2(116.865,150.965) ; v2(116.865,154.965) v1(117.265,154.565)
  PWR13 w0.152: v4(111.245,154.945) 111.625,154.565 v1(111.665,154.565) ; v2(112.865,154.965) v1(113.265,154.565) ; v4(115.265,154.965) v1(115.665,154.565)
  PWR13 w0.254: v1(109.265,148.965) v4(109.665,148.565) ; v1(110.065,149.765) 110.478,149.352 v4(110.49,149.352) 110.49,149.34 v1(110.865,148.965) v4(111.265,149.365) v1(111.665,149.765) ; v1(112.465,149.765) v4(112.865,149.365) ; v1(114.865,148.965) v2(115.265,149.365) v1(115.665,149.765) ; v1(116.465,148.965) v2(116.865,149.365) ; v1(116.465,150.565) v2(116.865,150.965)
  Bottom Layer w0.203: 124.5,141.34 U2.21@124.5,141.71
  Bottom Layer w0.254: v4(109.665,148.565) 109.88,148.35 C51.1@109.88,147.755 ; C45.1@109.874,149.164 110.302,149.164 v4(110.49,149.352) 110.49,150.046 C43.1@110.227,150.309 ; C47.1@110.928,148.785 111.264,149.121 111.264,149.135 v4(111.265,149.365) ; C112.1@111.245,154.119 v4(111.245,154.945) ; C44.1@112.798,148.785 112.865,148.852 v4(112.865,149.365) ; v2(112.865,154.965) 112.865,154.471 C113.1@113.217,154.119 ; C114.1@115.151,150.309 115.151,149.479 v2(115.265,149.365) 115.464,149.166 C72.1@115.464,148.785 ; C54.1@115.151,154.119 115.151,154.851 v4(115.265,154.965) ; v2(116.865,149.365) 116.981,149.365 117.463,148.883 C42.1@117.463,148.785 ; v2(116.865,150.965) 117.151,151.251 C115.1@117.151,151.579 ; v3(122.58,139.065) 123.393,139.065 124.5,140.172 124.5,141.34
  Bottom Layer w0.381: C128.1@113.576,141.265 115.116,141.265 116.087,140.294 R63.1@116.087,139.249
  other v2: 111.265,149.365 112.865,149.365 115.265,154.965
  other v3: 112.852,142.113
  other v4: 115.265,149.365 116.865,149.365 116.865,150.965 112.865,154.965
VCC-1V8: C33.1 C116.1 C117.1 C118.1 C119.1 C120.1 C121.1 C122.1 C123.1 C124.1 C136.1 C137.1 C248.2 C250.2 F1.1 F3.1 F6.1 R10.1 U1.F8 U1.F11 U1.G9 U1.H8 U1.J11 U1.K8 U1.L11 U1.M8 U1.N9 U1.N11 U1.P10 U1.R9 U12.28 U12.30 U14.7 U14.8 | length 51.7
  Top Layer w0.254: C136.1@101.6,147.83 C137.1@103.505,147.83 103.505,147.034 ; R10.1@102.841,138.303 v9(102.841,138.944) ; v2(109.665,153.365) v1(110.065,152.965) ; v2(110.465,152.565) v1(110.865,152.165) ; v4(111.265,150.965) U1.N11@111.665,151.365 ; v2(111.265,153.365) v1(111.665,152.965) ; v2(112.065,154.165) v1(112.465,153.765) ; v2(112.865,150.965) U1.L11@113.265,151.365 ; U1.K8@114.065,153.765 v2(114.465,154.165) ; U1.J11@114.865,151.365 v2(115.265,150.965) ; U1.H8@115.665,153.765 v2(116.065,154.165) ; U1.G9@116.465,152.965 U1.F8@117.265,153.765 ; U1.F11@117.265,151.365 v2(117.665,150.965) ; C248.2@125.73,139.475 v3@126.352,139.475 ; U12.28@126.75,141.11 126.75,140.442 v6(126.8,140.392) 126.352,139.944 v3@126.352,139.475 ; U12.30@127.75,141.11 127.75,140.542 v6(127.6,140.392) 127.6,139.69 127.385,139.475 C250.2@127,139.475 v3@126.393,139.475 ; v3@126.352,139.475 v3@126.393,139.475 ; v3@126.352,139.475 v3(126.352,139.434) v3@126.393,139.475
  ART10 w0.508: v1(103.505,138.938) 104.038,138.405 104.038,137.312 104.927,136.423 108.407,136.423 110.528,138.544 v3(110.528,141.154)
  GND02 w0.254: v9(102.841,138.944) 103.499,138.944 v1(103.505,138.938) ; v2(109.665,153.365) v1(110.065,152.965) ; v2(110.465,152.565) v1(110.865,152.165) ; v1(110.865,150.565) v4(111.265,150.965) ; v2(111.265,153.365) v1(111.665,152.965) ; v2(112.065,154.165) v1(112.465,153.765) ; v1(112.465,150.565) v2(112.865,150.965) ; v2(114.465,154.165) v1(114.865,153.765) ; v1(114.865,150.565) v2(115.265,150.965) ; v2(116.065,154.165) v1(116.465,153.765) ; v2(116.865,153.365) v1(117.265,152.965) ; v1(117.265,150.565) v2(117.665,150.965)
  PWR13 w0.152: v4(114.465,150.965) v1(114.865,150.565) v2(115.265,150.965)
  PWR13 w0.254: v1(110.865,150.565) v4(111.265,150.965) ; v2(111.265,153.365) v1(111.665,152.965) ; v1(112.465,153.765) v4(112.865,153.365) ; v4(116.065,153.365) v1(116.465,153.765)
  Bottom Layer w0.254: C33.1@110.227,151.579 C124.1@111.309,151.579 111.309,151.009 v4(111.265,150.965) 111.309,150.921 C120.1@111.309,150.309 ; v2(111.265,153.365) 111.309,153.321 C121.1@111.309,152.692 ; v4(112.865,153.365) 113.081,153.365 113.217,153.229 C119.1@113.217,152.692 ; C123.1@114.037,150.309 114.465,150.737 v4(114.465,150.965) 114.465,151.151 C122.1@114.037,151.579 ; C117.1@115.151,151.579 115.151,151.079 v2(115.265,150.965) ; C118.1@115.971,152.692 115.971,153.271 v4(116.065,153.365) ; C116.1@122.653,151.72 123.653,151.72 123.825,151.892 v3(123.825,152.273)
  Bottom Layer w0.381: v4(110.528,139.376) 110.281,139.376 109.98,139.677 109.98,140.606 v3(110.528,141.154) ; F6.1@122.72,154.866 122.847,154.993 v3(122.847,155.632)
  Bottom Layer w0.508: v3(119.38,137.211) 119.128,136.959 F1.1@119.128,136.398 119.128,136.117 v3(119.583,135.661)
  other v2: 111.265,150.965
  other v4: 115.265,150.965 111.265,153.365
  other v6: 100.889,147.015 101.321,147.015
  other v11: 101.879,147.015 102.489,147.015 103.124,147.015
VCC-IN: C79.1 C80.1 C129.1 C132.1 C133.1 C138.1 C139.1 J1.2 J1.3 J1.4 J1.52 J1.53 J1.54 J2.47 J2.48 J2.49 J2.97 J2.98 J2.99 J3.47 J3.48 J3.49 J3.97 J3.98 J3.99 R6.2 R7.1 R11.1 R25.1 U10.19 U10.20 U10.21 U10.33 U11.13 U11.14 U14.13 U14.14 U15.5 U16.5 U19.13 U19.14 | length 58.3
  Top Layer w0.254: U14.14@100.735,143.53 U14.13@100.735,144.03 ; v6(100.889,142.621) 100.33,142.621 100.101,142.85 100.101,143.84 100.291,144.03 U14.13@100.735,144.03 ; v6(101.346,142.621) 101.422,142.697 101.422,143.814 101.206,144.03 U14.13@100.735,144.03 ; v3(101.549,138.938) 101.756,138.731 R11.1@101.756,138.303 ; U10.33@116.935,138.93 117.754,138.93 v3(117.816,138.868) ; R25.1@124.05,153.67 124.05,154.289 v3(124.086,154.325) ; U19.13@128.385,155.345 128.385,154.793 128.562,154.616 128.689,154.616 128.885,154.812 U19.14@128.885,155.345 ; v3(130.243,162.719) J3.97@131.9,162.719 ; J3.98@131.9,163.219 132.994,163.219 v10(133.248,162.965) ; J3.99@131.9,163.719 v10(133.248,163.719) ; v10(134.548,163.719) J3.49@135.9,163.719 ; J3.47@135.9,162.719 134.67,162.719 134.424,162.965 134.678,163.219 J3.48@135.9,163.219
  ART03 w0.254: v3(124.086,154.325) 124.777,155.016 126.467,155.016 127.629,153.854 v3(129.337,153.854)
  Bottom Layer w0.254: J1.4@100.782,162.719 v4(102.111,162.719) ; J1.3@100.782,163.219 v4(102.111,163.219) ; J1.2@100.782,163.719 v4(102.111,163.719) ; v10(103.528,163.219) 104.028,162.719 J1.54@105.182,162.719 ; v3(104.686,135.693) 105.067,135.312 105.702,135.312 106.045,134.969 U15.5@106.045,134.255 ; J1.53@105.182,163.219 103.535,163.219 104.035,163.719 J1.52@105.182,163.719 ; v3(113.792,134.042) 115.325,134.042 R6.2@116.214,134.931 ; U16.5@125.73,150.13 125.73,149.193 v3(125.895,149.028) ; R7.1@126.775,160.02 127.467,160.712 128.435,160.712 128.68,160.467 C133.1@128.68,160.02 ; U11.14@128.885,158.345 U11.13@128.385,158.345 128.385,157.746 128.499,157.632 129.311,157.632 129.438,157.759 v3(129.438,159.188) ; v3@130.227,162.719 v3(130.243,162.719) J2.97@131.7,162.719 ; J2.98@131.7,163.219 132.994,163.219 v10(133.248,162.965) ; J2.99@131.7,163.719 v10(133.248,163.719) ; v10(134.548,163.719) J2.49@136.1,163.719 ; J2.47@136.1,162.719 134.794,162.719 v10(134.548,162.965) 134.802,163.219 J2.48@136.1,163.219
  Bottom Layer w0.381: v3(129.337,151.949) 128.451,151.949 C132.1@128.27,152.13 129.048,152.908 v3(129.337,152.908)
  other v1: 100.965,140.97 101.6,140.995 100.99,141.656 101.6,141.656 101.573,162.719 100.885,162.73 100.885,163.691
  other v3: 112.166,134.042 112.979,134.042 129.438,159.95
  other v6: 100.889,142.164 101.346,142.164 101.778,142.164
VCFG0: R42.2 U1.D8 | length 2.5
  Top Layer w0.114: U1.D8@118.865,153.765 v2(119.265,154.165)
  GND02 w0.109: v2(119.265,154.165) v1(119.665,153.765)
  PWR13 w0.114: v4(119.265,153.365) v1(119.665,153.765)
  Bottom Layer w0.254: R42.2@119.097,154.119 119.097,153.533 v4(119.265,153.365)
WDI: U1.E6 U3.4 | length 19.4
  Top Layer w0.114: U1.E6@118.065,155.365 v2(118.465,155.765)
  Top Layer w0.254: v3(129.22,163.864) U3.4@129.22,165.13
  ART03 w0.102: v1(118.865,155.365) 119.119,155.365 119.488,155.734 119.895,155.734 120.073,155.912 120.073,156.395 120.276,156.598 122.384,156.598 122.511,156.471 123.908,156.471 125.247,157.81 127.838,157.81 128.753,158.725 128.753,163.397 v3(129.22,163.864)
  GND02 w0.109: v2(118.465,155.765) v1(118.865,155.365)
Z_MR_NRST: J2.18 J3.18 R14.2 U3.3 | length 33.4
  Top Layer w0.114: v3(134.548,148.219) J3.18@135.9,148.219
  Top Layer w0.508: U3.3@129.22,162.53 129.22,162.857 v3(130.244,163.881)
  ART03 w0.508: v3(130.244,163.881) 131.547,163.881 133.045,165.379 134.645,165.379 136.423,163.601 136.423,157.632 135.56,156.769 135.56,148.717 135.062,148.219 v3(134.548,148.219)
  Bottom Layer w0.114: v3(134.548,148.219) J2.18@136.1,148.219
  Bottom Layer w0.254: v3(130.244,163.881) 130.244,164.255 130.708,164.719 131.318,164.719 131.724,165.125 131.724,166.522 132.236,167.034 R14.2@132.236,167.386
Z_NRST: R45.1 U1.C7 U3.1 | length 18.4
  Top Layer w0.114: U1.C7@119.665,154.565 v2(120.065,154.965)
  Top Layer w0.254: v3(126.657,163.506) 127.32,162.843 U3.1@127.32,162.53
  ART10 w0.127: v1(120.465,154.565) 120.853,154.953 120.853,155.727 121.691,156.566 121.691,157.226 122.459,157.994 122.459,158.781
  ART10 w0.254: 122.459,158.781 122.459,159.061 123.012,159.614 124.104,159.614 126.848,162.357 126.848,163.315 v3(126.657,163.506)
  GND02 w0.109: v2(120.065,154.965) v1(120.465,154.565)
  PWR13 w0.114: v4(118.465,153.365) 118.465,154 118.643,154.178 120.078,154.178 v1(120.465,154.565)
  Bottom Layer w0.254: R45.1@117.844,152.692 v4@118.465,153.313
ZYNQA_I2C_SCL: J2.3 J3.3 U1.C5 | length 31.8
  Top Layer w0.114: U1.C5@119.665,156.165 v2(120.065,156.565) ; v3(134.007,140.719) J3.3@135.9,140.719
  ART03 w0.102: v1(120.465,156.165) 120.87,155.76 122.232,155.76 122.555,156.083 124.097,156.083 124.504,156.489 126.277,156.489 127.09,155.677 129.007,155.677 131.572,153.111 131.572,151.181 132.867,149.885 132.867,141.351 133.045,141.173 133.553,141.173 v3(134.007,140.719)
  GND02 w0.109: v2(120.065,156.565) v1(120.465,156.165)
  Bottom Layer w0.114: v3(134.007,140.719) J2.3@136.1,140.719
ZYNQA_I2C_SDA: J2.2 J3.2 U1.C8 | length 33.2
  Top Layer w0.114: U1.C8@119.665,153.765 v2(120.065,154.165) ; v3(134.548,140.219) J3.2@135.9,140.219
  ART03 w0.102: v1(123.647,155.626) 124.104,155.626 124.689,156.21 126.06,156.21 126.975,155.296 128.88,155.296 131.216,152.959 131.216,151.028 132.588,149.657 132.588,140.132 133.096,139.624 133.953,139.624 v3(134.548,140.219)
  ART05 w0.109: v1(120.465,153.765) 120.694,153.765 121.107,154.178 122.555,154.178 123.647,155.27 v1(123.647,155.626)
  GND02 w0.109: v2(120.065,154.165) v1(120.465,153.765)
  Bottom Layer w0.114: v3(134.548,140.219) J2.2@136.1,140.219
pads on no net: Designator16_7.0 Designator16_7.1 Designator16_8.0 Designator16_8.1 Designator16_9.0 Designator16_9.1 Designator16_10.0 Designator16_10.1 Designator16_11.0 Designator16_11.1 Designator16_12.0 Designator16_12.1 Designator16_13.0 Designator16_13.1 Designator16_14.0 Designator16_14.1 G1.1 J1. J2. J3. RR7.5 U1.B5 U1.N16 U1.T5 U1.T9 U1.U5 U1.U7 U1.U8 U1.U9 U1.U10 U1.V5 U1.V6 U1.V7 U1.V8 U1.V10 U1.V11 U1.W6 U1.W8 U1.W9 U1.W10 U1.W11 U1.Y6 U1.Y7 U1.Y8 U1.Y9 U1.Y11 U1.Y12 U1.Y13 U5.9 U6.F1 U6.G7 U6.J1 U6.J9 U6.L1 U6.L9 U6.M7 U8.F1 U8.G7 U8.J1 U8.J9 U8.L1 U8.L9 U8.M7 U10.1 U10.2 U10.3 U10.4 U10.12 U10.22 U10.23 U10.24 U10.25 U10.29 U10.34 U10.35 U10.36 U10.37 U10.38 U11.1 U11.6 U11.15 U11.16 U12.12 U12.15 U12.16 U12.25 U14.1 U14.6 U14.15 U14.16 U19.1 U19.6 U19.15 U19.16

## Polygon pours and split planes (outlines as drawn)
GND on Top Layer "Top Layer-No Net" (hatched 90Degree grid 0.102 track 0.102, remove dead copper, pour order 1002): 104.445,149.028 104.445,150.425 101.003,150.425 100.749,150.171 100.749,149.155 100.876,149.028
VCC-1V8 on Top Layer "Top Layer-No Net" (hatched 90Degree grid 0.102 track 0.102, remove dead copper, pour order 1001): 103.765,146.488 101.13,146.488 100.876,146.742 100.876,147.885 101.13,148.139 103.911,148.139 103.911,146.634
GND on Top Layer "Top Layer-No Net" (hatched 90Degree grid 0.102 track 0.102, remove dead copper, pour order 1001): 125.641,154.235 124.371,154.235 123.99,154.616 123.99,155.759 124.117,155.886 125.573,155.886 125.61,155.849 126.245,155.849 126.385,155.709 126.385,154.852 126.276,154.743 125.768,154.235 125.641,154.235
VCC-IN on Top Layer "Top Layer-No Net" (solid, remove dead copper, pour order 1003): 112.052,135.566 111.671,135.185 111.671,134.042 112.052,133.661 113.83,133.661 114.211,134.042 114.211,135.539 114.184,135.566
GND on Top Layer "Top Layer-No Net" (hatched 90Degree grid 0.102 track 0.102, remove dead copper, pour order 1002): 124.625,159.696 123.228,159.696 123.101,159.823 123.101,160.966 123.355,161.22 124.625,161.22 124.879,160.966 124.879,159.95
VCC-IN on Top Layer "Top Layer-No Net" (hatched 90Degree grid 0.102 track 0.102, remove dead copper, pour order 1003): 130.086,155.759 128.799,155.759 128.385,155.345 128.385,153.169 128.308,153.092 127.927,152.711 127.927,151.949 128.181,151.695 130.086,151.695 130.213,151.822 130.213,155.632 130.086,155.759
BANK13_VCC on Top Layer "Top Layer-No Net" (hatched 90Degree grid 0.102 track 0.102, remove dead copper, pour order 1004): 127.165,167.443 126.149,167.443 126.022,167.316 126.022,164.649 126.149,164.522 127.292,164.522 127.419,164.649 127.419,167.189
GND on Top Layer "Top Layer-No Net" (hatched 90Degree grid 0.102 track 0.102, remove dead copper, pour order 1005): 132.236,167.386 131.864,167.014 131.864,165.411 132.118,165.157 132.753,165.157 132.88,165.284 132.88,166.948 132.442,167.386
ADDRVREF on Top Layer "Top Layer-No Net" (solid, remove dead copper, pour order 1006): 131.61,167.443 131.61,165.284 131.483,165.157 130.594,165.157 130.467,165.284 130.467,167.443
VCC-1V0 on Top Layer "Top Layer-No Net" (hatched 90Degree grid 0.102 track 0.102, remove dead copper, pour order 1000): 114.719,139.249 112.179,139.249 111.925,139.503 111.925,142.932 112.306,143.313 114.592,143.313 114.846,143.059 114.846,142.678 114.719,142.551
BANK13_VCC on Top Layer "Top Layer-No Net" (solid, remove dead copper, pour order 1000): 122.387,156.595 122.003,156.979 122.003,158.63 122.434,159.061 125.419,159.061 125.895,158.585 125.895,157.918 126.149,157.664 126.657,157.664 126.784,157.537 126.784,156.775 126.604,156.595
VCC-IN on Top Layer "Top Layer-No Net" (hatched 90Degree grid 0.102 track 0.102, remove dead copper, pour order 1000): 100.368,144.075 100.114,143.821 100.114,141.662 100.241,141.535 100.749,141.535 101.511,140.773 102.146,140.773 102.146,142.304 101.511,142.939 101.511,143.821 101.257,144.075
AHVDD_CA on Bottom Layer "Top Layer-No Net" (hatched 90Degree grid 0.102 track 0.102, remove dead copper, pour order 1007): 126.32,156.267 122.461,156.267 122.257,156.471 122.257,158.528 122.79,159.061 125.26,159.061 125.768,158.553 125.768,157.918 126.022,157.664 126.46,157.664 126.594,157.531 126.594,156.54
VCC-IN on Bottom Layer "Top Layer-No Net" (solid, remove dead copper, pour order 1004): 114.084,133.788 112.052,133.788 111.557,134.283 111.557,135.579 112.052,136.074 113.957,136.074 114.338,135.693 114.338,134.042
GND on Bottom Layer "Top Layer-No Net" (solid, remove dead copper, pour order 1005): 114.846,139.757 111.671,139.757 111.29,139.376 111.29,137.432 112.426,136.296 114.224,136.296 115.227,137.3 115.227,139.376
GND on Bottom Layer "Top Layer-No Net" (hatched 90Degree grid 0.102 track 0.102, remove dead copper, pour order 1008): 125.514,155.759 124.371,155.759 124.117,155.505 124.117,154.743 124.371,154.489 124.625,154.235 125.133,154.235 125.895,154.235 126.022,154.362 126.022,155.632 125.895,155.759 125.514,155.759
GND on Bottom Layer "Top Layer-No Net" (hatched 90Degree grid 0.102 track 0.102, remove dead copper, pour order 1009): 124.879,160.331 124.879,159.823 124.752,159.696 123.228,159.696 123.101,159.823 123.101,160.712 123.101,160.966 123.228,161.093 123.355,161.22 124.117,161.22 124.752,161.22 124.879,161.093 124.879,160.331
GND on Bottom Layer "Top Layer-No Net" (hatched 90Degree grid 0.102 track 0.102, remove dead copper, pour order 1012): 129.324,167.062 127.673,167.062 127.546,167.189 127.546,169.729 127.673,169.856 128.181,169.856 128.435,169.602 128.435,169.094 129.324,168.205
BANK13_VCC on Bottom Layer "Top Layer-No Net" (hatched 90Degree grid 0.102 track 0.102, remove dead copper, pour order 1013): 130.721,168.078 130.086,168.078 129.705,167.697 129.705,166.554 129.22,166.069 129.22,164.88 129.451,164.649 129.902,164.649 130.721,165.468
VCC-1V0 on Bottom Layer "Top Layer-No Net" (hatched 90Degree grid 0.102 track 0.102, remove dead copper, pour order 1001): 111.1,140.9 115.227,140.9 115.354,141.027 115.354,142.678 115.1,142.932 111.512,142.932 111.1,142.519
VCC-IN on Bottom Layer "Top Layer-No Net" (hatched 90Degree grid 0.102 track 0.102, remove dead copper, pour order 1011): 128.435,160.331 128.435,159.042 128.168,158.775 128.168,157.804 128.435,157.537 129.451,157.537 129.705,157.791 129.705,160.077 129.451,160.331
VCC-1V8 on ART03 "Top Layer-No Net" (solid, remove dead copper, pour order 1000): 103.353,146.507 102.464,145.618 101.168,145.618 100.457,145.618 100.355,145.72 100.355,147.625 100.559,147.828 102.87,147.828 103.581,147.117 103.581,146.736 103.353,146.507
AVTT on ART03 "TOP-No Net" (solid, remove dead copper, pour order 1000): 126.238,170.18 124.714,170.18 124.46,169.926 124.46,161.798 124.714,161.544 126.238,161.544 126.492,161.798 126.492,169.926 126.238,170.18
